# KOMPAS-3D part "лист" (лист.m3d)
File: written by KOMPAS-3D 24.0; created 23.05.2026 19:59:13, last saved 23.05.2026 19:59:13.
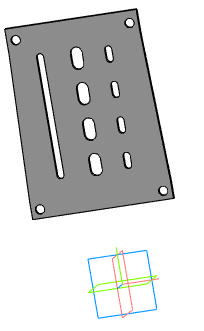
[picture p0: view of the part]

Document properties: Автор: R2D2; Полное имя файла: E:\Работа\Зайцев\GVKR1331E-1W-Fb-2P Задвижка шиберная DN.ru Ду50-300 Ру16-10-6\исходные материалы\DN50\111\лист.m3d

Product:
- Part/product: лист
    Масса: 0.527465
    Раздел спецификации: Прочие изделия
    Примечание: D040-08800

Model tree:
1. Эскиз:1  (with: Грань.Элемент выдавливания:15, Вершина.Элемент выдавливания:15, Ребро.Элемент выдавливания:15, Вершина.Элемент выдавливания:5, Ребро.Элемент выдавливания:5, Вершина.Скругление:1)  (labels: Затвор дисковый DN.ru Ду200 Ру16)
2. Элемент выдавливания:1
3. Эскиз:2  (with: Грань.Элемент выдавливания:1)
4. Элемент выдавливания:2
5. Эскиз:3  (with: Грань.Элемент выдавливания:1, Ребро.Элемент выдавливания:1)
6. Элемент выдавливания:3
7. Эскиз:4  (with: Грань.Элемент выдавливания:1, Вершина.Элемент выдавливания:2)
8. Элемент выдавливания:4
9. Массив по сетке:1  (with: Элемент выдавливания:4, Эскиз:4, Ребро.Элемент выдавливания:2)  (4 pattern instances)
     Шаг 1 = 30; Угол раствора = 90
10. Зеркальный массив:1
11. Экземпляр ( 1 )
12. Экземпляр ( 2 )  (with: Элемент выдавливания:3)

Expressions: v444*0.6
Referenced files in E:\Работа\Зайцев\GVKR1331E-1W-Fb-2P Задвижка шиберная DN.ru Ду50-300 Ру16-10-6\исходные материалы\DN50\111\: GVKR1331E-1W-Fb-2P Задвижка шиберная DN.ru Ду50 Ру16.a3d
